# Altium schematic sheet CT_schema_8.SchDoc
size 278 x 170 mm
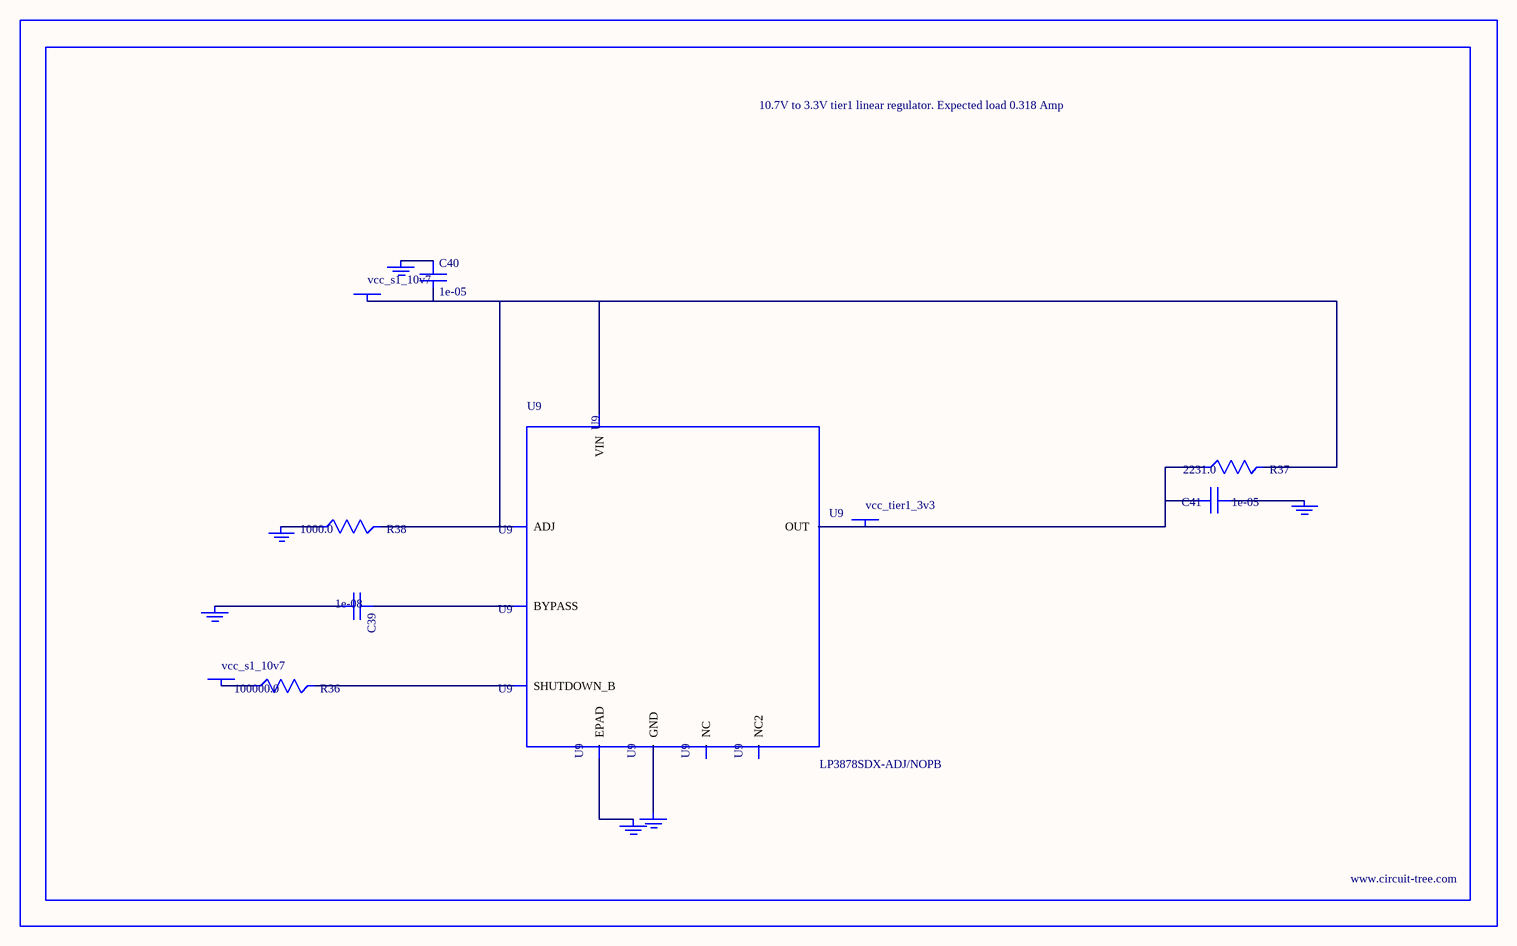
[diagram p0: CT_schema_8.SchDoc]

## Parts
BORDER7  (no value)
C39  1e-08  [C0402]
C40  1e-05  [C1206]
C41  1e-05  [C1210]
GND_INSTANCE_7_0  (no value)
GND_INSTANCE_7_1  (no value)
GND_INSTANCE_7_2  (no value)
GND_INSTANCE_7_3  (no value)
GND_INSTANCE_7_4  (no value)
GND_INSTANCE_7_5  (no value)
POWER_INSTANCE_7_0  vcc_s1_10v7
POWER_INSTANCE_7_1  vcc_s1_10v7
POWER_INSTANCE_7_2  vcc_tier1_3v3
R36  100000.0  [R0603]
R37  2231.0  [R0603]
R38  1000.0  [R0603]
U9  LP3878SDX-ADJ/NOPB  [WSON-8]

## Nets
NetC39_1: C39.1 U9.1(BYPASS)
NetC39_2: C39.2 GND_INSTANCE_7_0.0(GND)
NetC40_1: C40.1 GND_INSTANCE_7_1.0(GND)
NetC40_2: C40.2 POWER_INSTANCE_7_0.0(PWR) R37.2 R38.2 U9.4(VIN) U9.6(ADJ)
NetC41_1: C41.1 GND_INSTANCE_7_2.0(GND)
NetC41_2: C41.2 POWER_INSTANCE_7_2.0(PWR) R37.1 U9.5(OUT)
NetGND_INSTANCE_7_3_0: GND_INSTANCE_7_3.0(GND) R38.1
NetGND_INSTANCE_7_4_0: GND_INSTANCE_7_4.0(GND) U9.PAD(EPAD)
NetGND_INSTANCE_7_5_0: GND_INSTANCE_7_5.0(GND) U9.3(GND)
NetPOWER_INSTANCE_7_1_0: POWER_INSTANCE_7_1.0(PWR) R36.1
NetR36_2: R36.2 U9.8(SHUTDOWN_B)

Not connected (* = marked no-connect by the designer): U9 2(NC) 7(NC2)

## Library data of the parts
BORDER7 = BORDER_PAGE7
C39 = C0402C103K3RAC
C40 = C1206C106K3RACTU
C41 = GRM32DR61E106MA12L
GND_INSTANCE_7_0-GND_INSTANCE_7_5 = GND
POWER_INSTANCE_7_0-POWER_INSTANCE_7_2 = PWR
R36 = RC0603JR-07100KL
R37 = R37
R38 = RC0603JR-071KL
